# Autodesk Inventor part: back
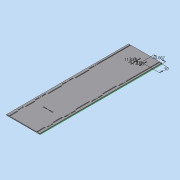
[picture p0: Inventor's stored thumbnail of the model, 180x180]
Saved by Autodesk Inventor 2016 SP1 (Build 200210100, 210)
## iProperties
Created: 2016-06
Part Number: back
Material: Generic
Document SubType Name: Modeling
Designer: Mohamed A.
Density: 1 g/cm^3
Appearance: Default
Author: Mohamed A.
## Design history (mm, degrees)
sketch "Sketch1"
  geometry: L1 (-57, 160)-(57, 160); L2 (57, 160)-(57, -160); L3 (57, -160)-(-57, -160); L4 (-57, -160)-(-57, 160); L5 (-57, 160)-(57, -160); L6 (57, 160)-(-57, -160); 1 further point
  constraints: 12 end point, 2 midpoint, 2 parallel, 1 horizontal, 1 perpendicular
  dimensions: "d0" = 114 distance of L2.end L3.end; "d1" = 320 distance of L1.end L2.end
extrude "Extrusion1" new body sketch "Sketch1" distance "d2" = 3; taper "d3" = 0 deg
sketch "Sketch2"
  geometry: L1 (52, 140.75)-(52, 137.65) reference; L2 (52, 140.75)-(49, 140.75) reference; L3 (49, 137.65)-(49, 140.75) reference; L4 (52, 137.65)-(49, 137.65) reference; L5 (52, 45.05)-(52, 41.95) reference; L6 (52, 45.05)-(49, 45.05) reference; L7 (49, 41.95)-(49, 45.05) reference; L8 (52, 41.95)-(49, 41.95) reference; L9 (-49, 45.05)-(-49, 41.95) reference; L10 (-49, 45.05)-(-52, 45.05) reference; L11 (-52, 41.95)-(-52, 45.05) reference; L12 (-49, 41.95)-(-52, 41.95) reference; L13 (-49, 140.75)-(-49, 137.65) reference; L14 (-49, 140.75)-(-52, 140.75) reference; L15 (-52, 137.65)-(-52, 140.75) reference; L16 (-49, 137.65)-(-52, 137.65) reference; L17 (52, -48.15)-(52, -51.25) reference; L18 (52, -48.15)-(49, -48.15) reference; L19 (49, -51.25)-(49, -48.15) reference; L20 (52, -51.25)-(49, -51.25) reference; L21 (-49, -48.15)-(-49, -51.25) reference; L22 (-49, -48.15)-(-52, -48.15) reference; L23 (-52, -51.25)-(-52, -48.15) reference; L24 (-49, -51.25)-(-52, -51.25) reference; L25 (52, -116.45)-(52, -119.55) reference; L26 (52, -116.45)-(49, -116.45) reference; L27 (49, -119.55)-(49, -116.45) reference; L28 (52, -119.55)-(49, -119.55) reference; L29 (-49, -116.45)-(-49, -119.55) reference; L30 (-49, -116.45)-(-52, -116.45) reference; L31 (-52, -119.55)-(-52, -116.45) reference; L32 (-49, -119.55)-(-52, -119.55) reference; L33 (-49, -114.25)-(-52, -114.25) reference; L34 (-52, -114.25)-(-52, -109) reference; L35 (-52, -109)-(-49, -109) reference; L36 (-49, -109)-(-49, -114.25) reference; L37 (-52, -121.75)-(-49, -121.75) reference; L38 (-49, -121.75)-(-49, -127) reference; L39 (-49, -127)-(-52, -127) reference; L40 (-52, -127)-(-52, -121.75) reference; L41 (-52, 39)-(-49, 39) reference; L42 (-49, 39)-(-49, 25.2) reference; L43 (-49, 25.2)-(-52, 25.2) reference; L44 (-52, 25.2)-(-52, 39) reference; L45 (-49, 48)-(-52, 48) reference; L46 (-52, 48)-(-52, 61.8) reference; L47 (-52, 61.8)-(-49, 61.8) reference; L48 (-49, 61.8)-(-49, 48) reference; L49 (-52, 134.7)-(-49, 134.7) reference; L50 (-49, 134.7)-(-49, 118.4) reference; L51 (-49, 118.4)-(-52, 118.4) reference; L52 (-52, 118.4)-(-52, 134.7) reference; L53 (-49, 143.7)-(-52, 143.7) reference; L54 (-52, 143.7)-(-52, 160) reference; L55 (-52, 160)-(-49, 160) reference; L56 (-49, 160)-(-49, 143.7) reference; L57 (-52, -54.2)-(-49, -54.2) reference; L58 (-49, -54.2)-(-49, -68) reference; L59 (-49, -68)-(-52, -68) reference; L60 (-52, -68)-(-52, -54.2) reference; L61 (-49, -45.2)-(-52, -45.2) reference; L62 (-52, -45.2)-(-52, -31.4) reference; L63 (-52, -31.4)-(-49, -31.4) reference; L64 (-49, -31.4)-(-49, -45.2) reference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; C1 r 1.4 at (50.5, 139.2); C2 r 1.4 at (-50.5, 139.2); C3 r 1.4 at (-50.5, 43.5); C4 r 1.4 at (50.5, 43.5); C5 r 1.4 at (50.5, -49.7); C6 r 1.4 at (-50.5, -49.7); C7 r 1.4 at (50.5, -118); C8 r 1.4 at (-50.5, -118); C9 r 1.4 at (0, 128.5); C10 r 1.4 at (0, -74.5)
  constraints: 224 end point, 56 horizontal, 56 vertical, 10 centre point, 112 other
  dimensions: "d10" = 2.8 diameter of C1; "d11" = 2.8 diameter of C2; "d12" = 2.8 diameter of C3; "d13" = 2.8 diameter of C4; "d14" = 2.8 diameter of C5; "d15" = 2.8 diameter of C6; "d16" = 2.8 diameter of C7; "d17" = 2.8 diameter of C8; "d18" = 2.8 diameter of C9; "d19" = 2.8 diameter of C10; "d20" = 40.66667 distance between parallel lines of L153 L139 (derived); "d21" = 11.83333 distance between parallel lines of L139 L137 (derived); "d22" = 9 distance between parallel lines of L137 L143 (derived); "d23" = 11.83333 distance between parallel lines of L143 L141 (derived); "d24" = 30 distance between parallel lines of L154 L140 (derived)
extrude "Extrusion2" cut sketch "Sketch2" distance "d8" = 10; taper "d9" = 0 deg
sketch "Sketch3"
  geometry: L1 (98, -3)-(98, 0) reference; L2 (0, 0)-(98, 0) reference; L3 (0, 0)-(0, -3) reference; L4 (98, -3)-(0, -3) reference; L5 (-3, -3)-(-3, 0) reference; L6 (-8, 0)-(-3, 0) reference; L7 (-8, 0)-(-8, -3) reference; L8 (-3, -3)-(-8, -3) reference; L9 (101, 0)-(101, -3) reference; L10 (106, -3)-(101, -3) reference; L11 (106, 0)-(106, -3) reference; L12 (101, 0)-(106, 0) reference; 1 further point
extrude "Extrusion3" join sketch "Sketch3" distance "d25" = 100; taper "d26" = 0 deg
sketch "Sketch4"
  geometry: L1 (16.333, 230)-(4.5, 230); L2 (4.5, 230)-(4.5, 227); L3 (4.5, 227)-(16.333, 227); L4 (16.333, 227)-(16.333, 230); L5 (-4.5, 230)-(-16.333, 230); L6 (-16.333, 230)-(-16.333, 227); L7 (-16.333, 227)-(-4.5, 227); L8 (-4.5, 227)-(-4.5, 230); L9 (-57, 260)-(-57, -160) reference; L10 (-49, 260)-(49, 260) reference; L11 (4.5, 230)-(-4.5, 227); L12 (4.5, 227)-(-4.5, 230); C1 r 1.4 at (0, 228.5); 1 further point
  constraints: 20 end point, 4 parallel, 2 horizontal, 2 perpendicular, 1 centre point, 1 midpoint, 1 point on line
  dimensions: "d27" = 11.833 distance of L3.end L2.end; "d28" = 3 distance of L2.end L1.end; "d29" = 11.833 distance of L7.end L6.end; "d30" = 3 distance of L6.end L5.end; "d31" = 9 distance between parallel lines of L8 L2; "d32" = 40.667 distance between parallel lines of L9 L6; "d33" = 30 distance between parallel lines of L10 L5; "d34" = 2.8 diameter of C1
extrude "Extrusion4" cut sketch "Sketch4" distance "d35" = 100; taper "d36" = 0 deg
body "Solid1"
node "Reference6"
node "Reference7"
node "Reference8"
node "Reference9"
node "Reference10"
node "Reference11"
node "Reference12"
node "Reference13"
node "Reference14"
node "Reference15"
node "Projected Loop1"
node "Projected Loop2"
node "Projected Loop3"
